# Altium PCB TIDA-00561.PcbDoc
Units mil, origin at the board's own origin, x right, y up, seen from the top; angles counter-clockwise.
Board outline 1527.56 x 1133.86 mil, 2 copper layers (Top Layer, Bottom Layer), stack 62 mil thick; 40 components, 27 nets, 121 pads, 25 vias.
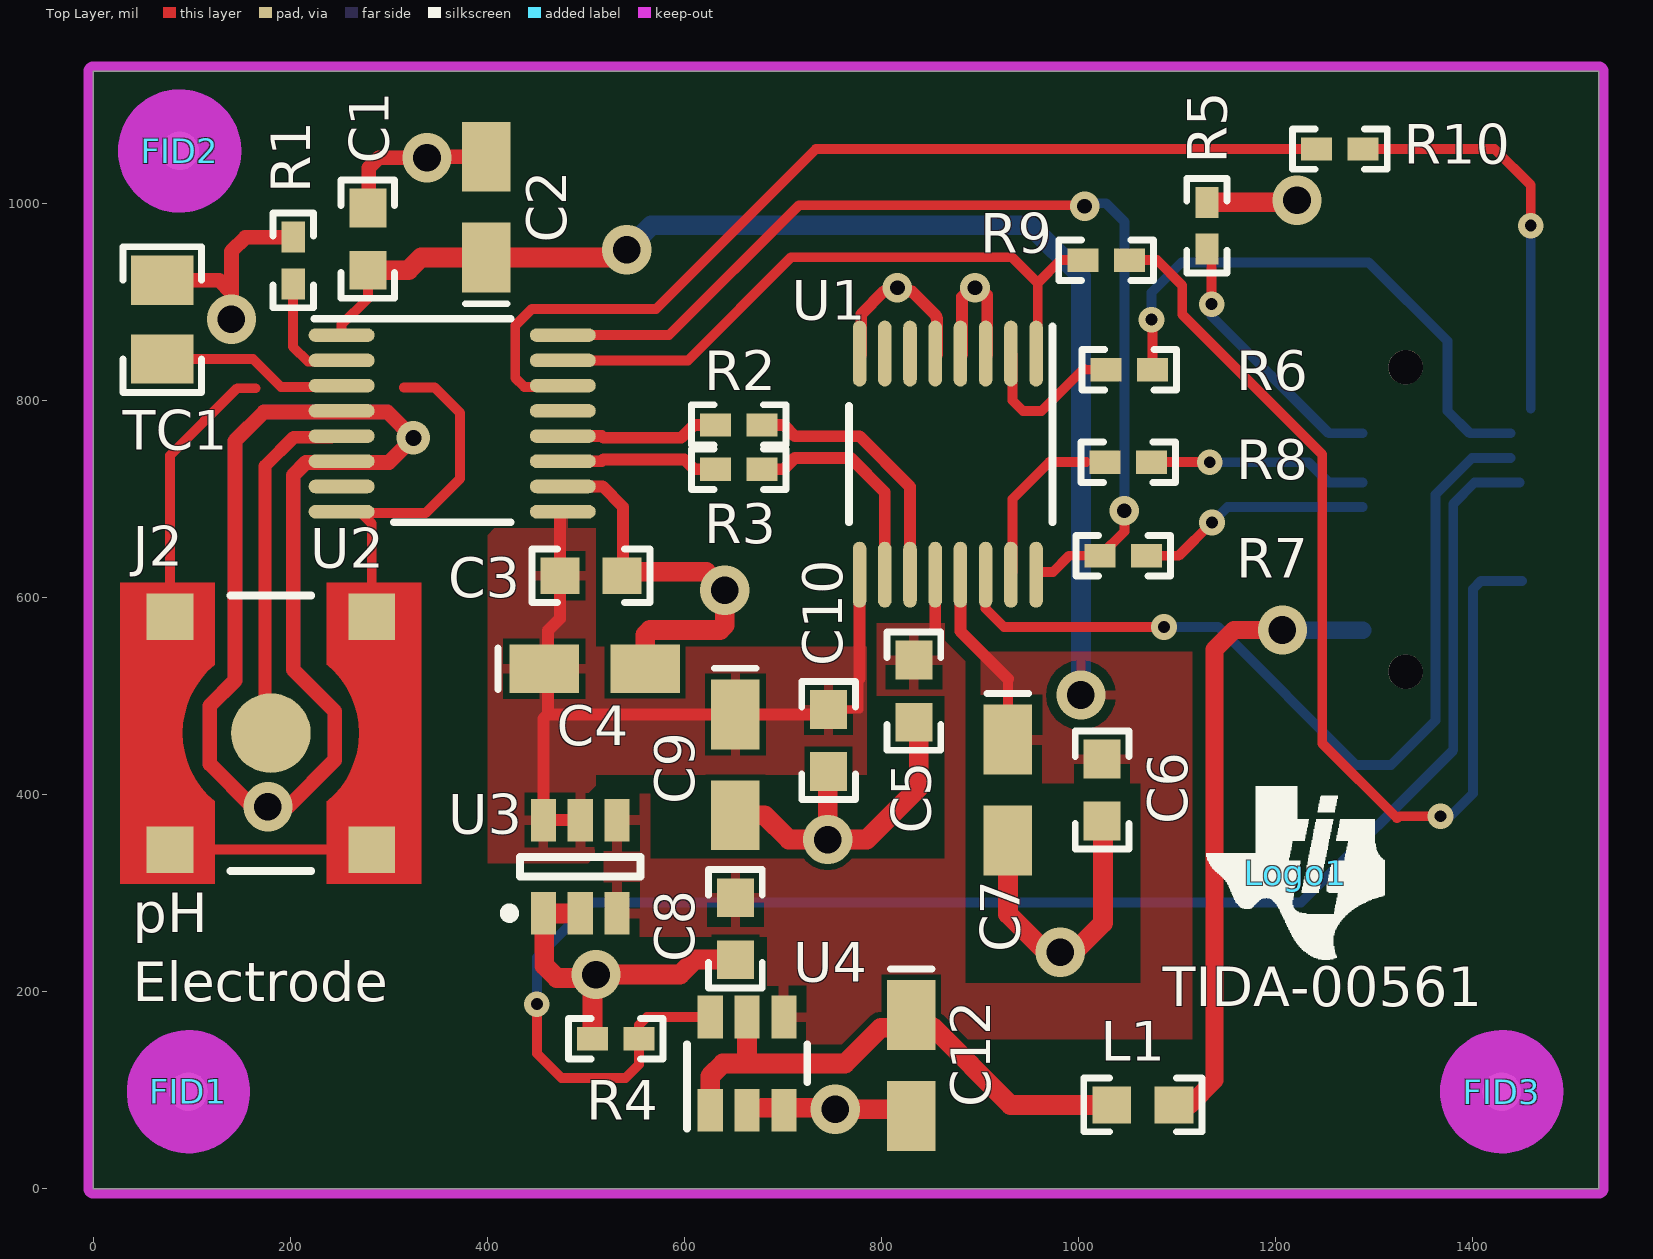
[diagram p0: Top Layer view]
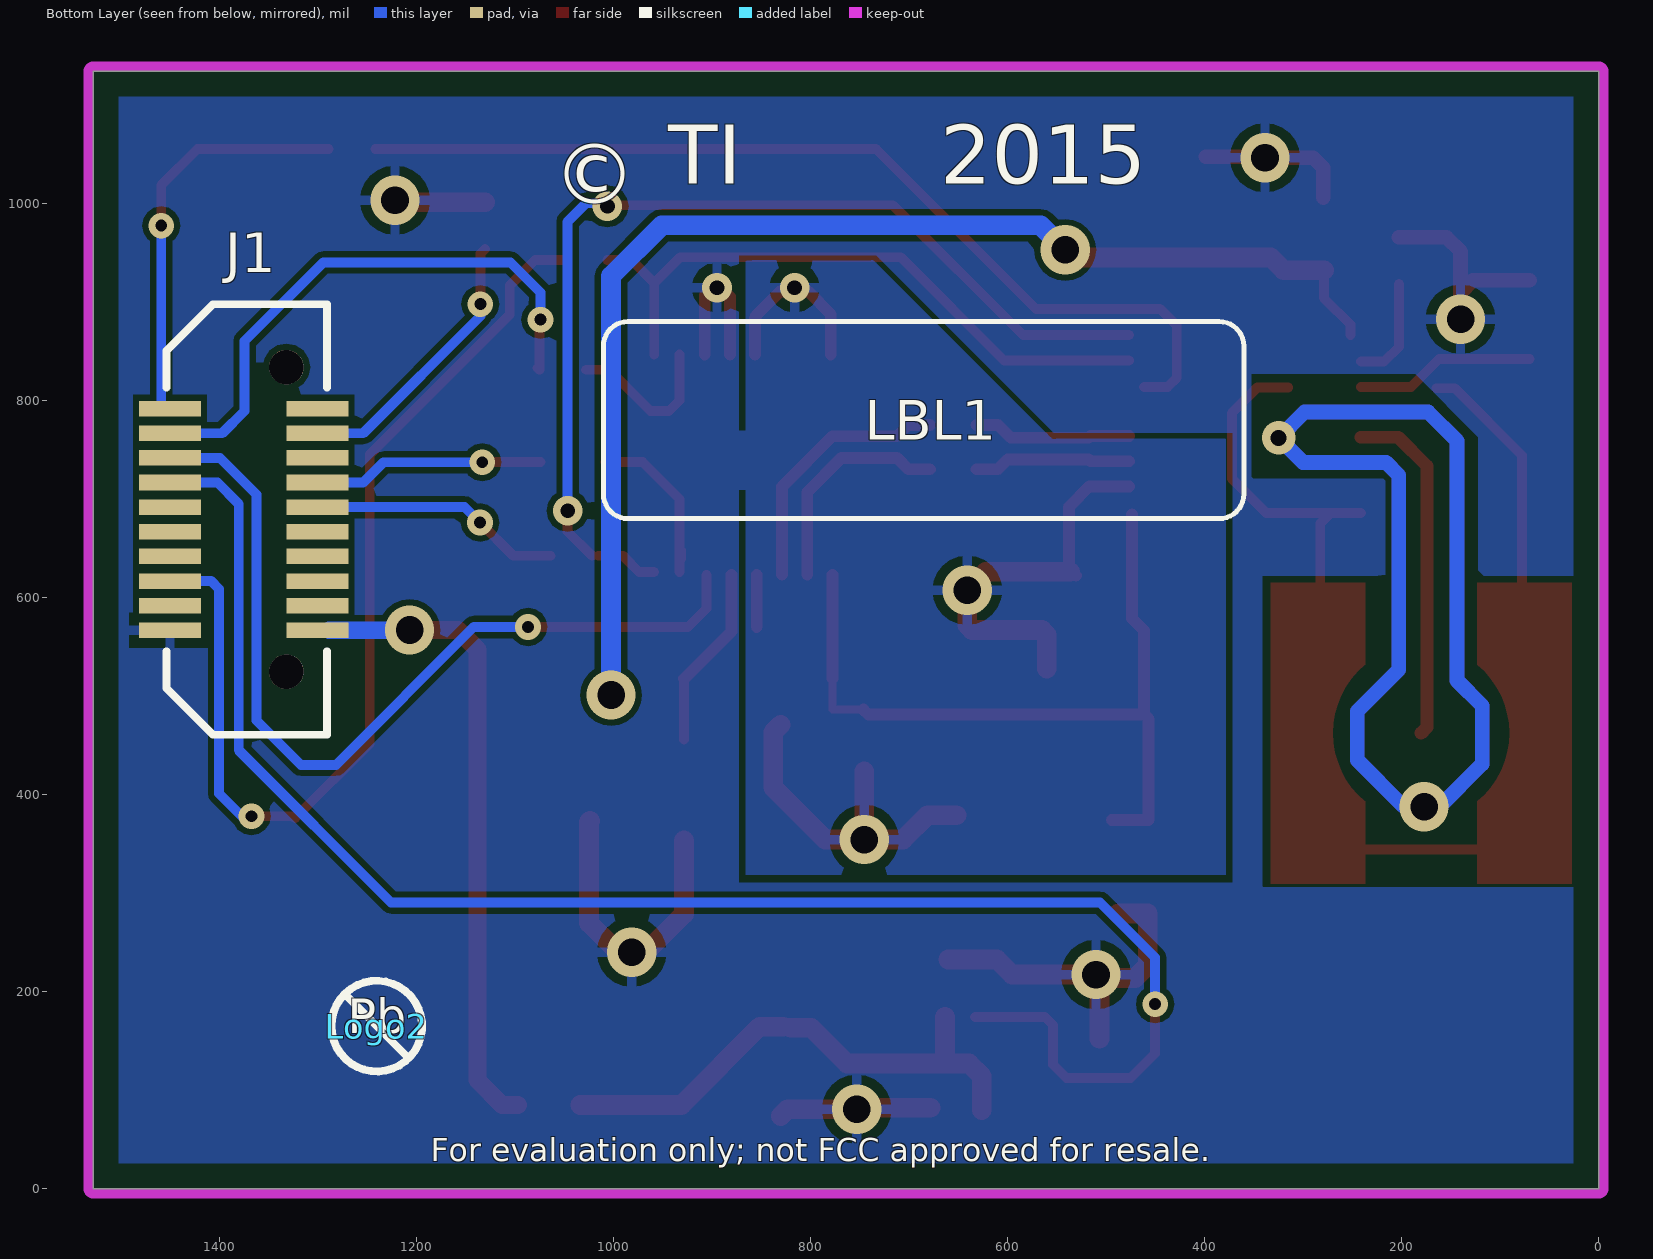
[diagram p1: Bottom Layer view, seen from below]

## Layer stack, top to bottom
Top Solder: solder mask 0.4, Solder Resist, Dk 3.5
Top Layer: signal copper 1.4
Dielectric1: core 59.2, FR-4, Dk 4.8
Bottom Layer: signal copper 1.4
Bottom Solder: solder mask 0.4, Solder Resist, Dk 3.5

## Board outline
0,0 1527.56,0 1527.56,1133.86 0,1133.86

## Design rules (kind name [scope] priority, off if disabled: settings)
AcuteAngle [All] p1: minimum=4.50000000000000E+0001 checktracksonly=FALSE
AssemblyTestPointUsage [All] p1: valid=2
Clearance Clearance_Keepouts [((IsTrack Or IsArc) And Not InPoly) And IsFree and IsKeepOut vs ((IsTrack Or IsArc) And Not InPoly) And IsFree and IsKeepOut] p1: gap=0
Clearance Clearance_BoardEdge_MountingHoles [OnCopper and InComponentClass('Mounting Holes') vs IsKeepOut] p2: gap=40
Clearance Clearance_BoardEdge_Poly [OnCopper and InPoly vs IsKeepOut] p3: gap=25
Clearance Clearance_BoardEdge [OnCopper and Not InComponentClass('Logo') and not InComponentClass('FiducialMark') and not InRegion(1000,500,4000,800) and Not IsKeepout vs IsKeepOut] p4: gap=25
Clearance Clearance_Poly [InPolygon] p5: gap=6
Clearance [All] p6: gap=7.87
ComponentClearance ComponentClearance_MountingHoles_FiducialMarks [InComponentClass('Mounting Holes') vs InComponentClass('FiducialMark')] p1: gap=50 collisioncheckmode=3 verticalgap=10 showdistances=FALSE
ComponentClearance ComponentClearance_Shunt [InComponentClass('Header') vs InComponentClass('Shunt')] p2: gap=0 collisioncheckmode=3 verticalgap=0 showdistances=FALSE
ComponentClearance ComponentClearance_Logo [InComponentClass('Logo')] p3: gap=50 collisioncheckmode=3 verticalgap=10 showdistances=FALSE
ComponentClearance ComponentClearance_ScrewToNut [(HasFootprint('NY PMS 440 0025 PH')) vs (HasFootprint('Keystone_1902C'))] p4: gap=5 collisioncheckmode=3 verticalgap=10 showdistances=FALSE
ComponentClearance ComponentClearance_MountingHoles [InComponentClass('Mounting Holes')] p5: gap=250 collisioncheckmode=3 verticalgap=100000 showdistances=FALSE
ComponentClearance ComponentClearance_SmallPassives [HasFootprint('0201*') or HasFootprint('0402*') or HasFootprint('0508') or HasFootprint('0603*') or HasFootprint('0612') or HasFootprint('0805*') or HasFootprint('0815*') or HasFootprint('0830*') or HasFootprint('1206*') or HasFootprint('1210*') or HasFootprint('1808*') or HasFootprint('1812*') or HasFootprint('1825*') or HasFootprint('2010*') or HasFootprint('2220*') or HasFootprint('2225*') or HasFootprint('2512*') or HasFootprint('2728*') or HasFootprint('3518*') vs HasFootprint('0201*') or HasFootprint('0402*') or HasFootprint('0508') or HasFootprint('0603*') or HasFootprint('0612') or HasFootprint('0805*') or HasFootprint('0815*') or HasFootprint('0830*') or HasFootprint('1206*') or HasFootprint('1210*') or HasFootprint('1808*') or HasFootprint('1812*') or HasFootprint('1825*') or HasFootprint('2010*') or HasFootprint('2220*') or HasFootprint('2225*') or HasFootprint('2512*') or HasFootprint('2728*') or HasFootprint('3518*')] p6: gap=20 collisioncheckmode=3 verticalgap=10 showdistances=FALSE
ComponentClearance ComponentClearance_THtoSMT [IsThruComponent vs IsSMTComponent] p7: gap=100 collisioncheckmode=3 verticalgap=30 showdistances=FALSE
ComponentClearance ComponentClearance_THtoTH [IsThruComponent vs IsThruComponent] p8: gap=118.11 collisioncheckmode=3 verticalgap=30 showdistances=FALSE
ComponentClearance [All] p9: gap=40 collisioncheckmode=3 verticalgap=10 showdistances=FALSE
DiffPairsRouting [All] p1: maxlimit=100 minlimit=10 mostfreqgap=10 toplayer_minwidth=12 toplayer_maxwidth=15 toplayer_prefwidth=15 bottomlayer_minwidth=12 bottomlayer_maxwidth=15 bottomlayer_prefwidth=15 maxuncoupledlength=1000
FabricationTestPointUsage TestPointUsage [All] p1: valid=2 allowmultiple=FALSE
FabricationTestpoint Testpoint [All] p1: side=3 testpointundercomponent=TRUE minsize=40 maxsize=100 preferedsize=60 minholesize=0 maxholesize=40 preferedholesize=32 testpointgrid=1 allowsidetop=TRUE allowsidebottom=TRUE usegrid=TRUE gridtolerance=0.01
FanoutControl Fanout_LCC [IsLCC] p1: bgadir=Out bgaviamode=Centered fanoutstyle=Auto fanoutdirection=Alternating viagrid=1 // Fanout_LCC (Default Rule)
FanoutControl Fanout_BGA [IsBGA] p2: bgadir=Out bgaviamode=Centered fanoutstyle=Auto fanoutdirection=Alternating viagrid=1 // Fanout_BGA (Default Rule)
FanoutControl Fanout_Default [All] p4: bgadir=Out bgaviamode=Centered fanoutstyle=Auto fanoutdirection=Alternating viagrid=1 // Fanout_Default (Default Rule)
FanoutControl Fanout_Small [(CompPinCount < 5)] p5: bgadir=Out bgaviamode=Centered fanoutstyle=Auto fanoutdirection=OutThenIn viagrid=1 // Fanout_Small (Default Rule)
HoleSize [All] p1: absolutevalues=TRUE maxlimit=251 minlimit=8 maxpercent=80.000 minpercent=20.000
MinimumAnnularRing MinimumAnnularRing_ThermalPadVias [IsVia and InAnyComponent] p1: minimumring=5.91
MinimumAnnularRing [All] p2: minimumring=7
MinimumSolderMaskSliver MinimumSolderMaskSliver_Logo [InComponentClass('Logo') vs InComponentClass('Logo')] p1: minsoldermaskwidth=0.7
MinimumSolderMaskSliver [All] p2: minsoldermaskwidth=3.94
NetAntennae [All] p1 off: netantennaetolerance=0
PlaneConnect [All] p1: planeconnectstyle=Relief reliefexpansion=10 reliefentries=4 reliefconductorwidth=10 reliefairgap=10
PolygonConnect [All] p1: connectstyle=Relief reliefconductorwidth=10 reliefentries=4 polygonreliefangle="90 Angle" airgapwidth=10
RoutingVias ThermalPadVias [IsVia and InAnyComponent] p1: holewidth=7.87 width=19.68 viastyle="Through Hole" minholewidth=7.87 minwidth=19.68 maxholewidth=12.99 maxwidth=23.62
RoutingVias [All] p2: holewidth=16 width=34 viastyle="Through Hole" minholewidth=7.87 minwidth=26 maxholewidth=40 maxwidth=65
SilkToBoardRegionClearance [Not ((IsComment or IsDesignator) And (Hide <> 'False')) and not InRegion(1000,500,4000,800)] p1:
SilkToSilkClearance SilkToSilkClearance_Pb-FreeLogo [(HasFootprint('Pb-Free_Overlay_Medium') OR HasFootprint('Pb-Free_Overlay_Small')) vs (HasFootprint('Pb-Free_Overlay_Medium') OR HasFootprint('Pb-Free_Overlay_Small'))] p1: silktosilkclearance=0
SilkToSilkClearance [All] p2: silktosilkclearance=5
SilkToSolderMaskClearance "Silk to Solder Mask Opening" [All] p1: minsilkscreentomaskgap=1 clearancetoexposedcopper=FALSE
SolderMaskExpansion [All] p1: expansion=1.97
UnpouredPolygon [All] p1: allowunpoured=FALSE
Width [All] p1: maxlimit=100 minlimit=6 preferedwidth=10 checkconnectedcopper=TRUE
13 further rules are at their usual default settings.

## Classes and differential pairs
component class Label: LBL1
component class AssemblyNote: ZZ1 ZZ2 ZZ3 ZZ4
component class Logo: Logo1
component class TIDA-00561_Hardware: FID1 FID2 FID3 LBL1 Logo1 Logo2 Logo3 ZZ1 ZZ2 ZZ3 ZZ4
component class FiducialMark: FID1 FID2 FID3
component class TIDA-00561_Wireless_pH: C1 C2 C3 C4 C5 C6 C7 C8 C9 C10 C12 J1 J2 L1 R1 R2 R3 R4 R5 R6 R7 R8 R9 R10 TC1 U1 U2 U3 U4
differential pair AIN: +AIN_P -AIN_N
differential pair VOUT: +VOUT_P -VOUT_N

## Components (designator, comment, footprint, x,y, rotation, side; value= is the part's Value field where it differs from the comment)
C1 "06035C104KAT2A" 0603 278.54,963.58 r90 top
C2 "293D106X0010A2TE3" 3216-18 398.62,996.06 r90 top
C3 "06035C104KAT2A" 0603 504.92,622.05 r0 top
C4 "293D106X0010A2TE3" 3216-18 508.8,527.56 r0 top
C5 "06035C104KAT2A" 0603 832.68,504.92 r270 top
C6 "06035C104KAT2A" 0603 1023.62,404.53 r270 top
C7 "293D106X0010A2TE3" 3216-18 928.15,404.53 r270 top
C8 "GRM188R71C474KA88D" 0603 651.57,263.78 r270 top
C9 "293D106X0010A2TE3" 3216-18 651.57,430.12 r270 top
C10 "06035C104KAT2A" 0603 746.06,454.72 r270 top
C12 "293D106X0010A2TE3" 3216-18 830,125 r270 top
FID1 "Fiducial" Fiducial10-30 96.46,98.43 r0 top
FID2 "Fiducial" Fiducial10-30 87.6,1053.15 r0 top
FID3 "Fiducial" Fiducial10-30 1429.13,98.43 r0 top
J1 "LSS-110-01-F-DV-A" Samtec_LSS-110-01-F-DV-A 1375,679.13 r90 bottom
J2 "CONSMA001-SMD-G" Linx_CONSMA001-SMD-G 180.11,462.27 r0 top
L1 "BLM18BB050SN1D" 0603 1065,85 r180 top
LBL1 "Size: 0.65\" x 0.20 \"" Label_650x200 685,780 r180 bottom
Logo1 "Texas Instruments" TI_Symbol_Overlay_Small 1220,320 r0 top
Logo2 "Pb-Free Symbol" Pb-Free_Overlay_Small 1240,165 r180 bottom
Logo3 "FCC disclaimer" FCC_disclaimer -4931.16,520 r180 bottom
R1 "RG1005P-101-B-T5" 0402 202.76,941.93 r270 top
R2 "CRCW04021K00JNED" 0402 655,775 r0 top
R3 "CRCW04021K00JNED" 0402 655,730 r0 top
R4 "CRCW04022M20JNED" 0402 530.23,152.27 r0 top
R5 "CRCW0402270KJNED" 0402 1130.11,977.27 r270 top
R6 "CRCW040247R0JNED" 0402 1051.32,830.99 r0 top
R7 "CRCW040247R0JNED" 0402 1045.11,642.27 r180 top
R8 "CRCW040247R0JNED" 0402 1050.11,737.27 r180 top
R9 "CRCW040247R0JNED" 0402 1027.7,942.27 r0 top
R10 "CRCW040247R0JNED" 0402 1265,1055 r0 top
TC1 "PTS080501B100RP100" 0805_HV 69.88,881.89 r90 top
U1 "ADS1120IPWR" PW0016A_N 867.11,735.27 r270 top
U2 "LMP91200MTX/NOPB" PW0016A_N 364.17,776.57 r0 top
U3 "REF3220AIDBVR" DBV0006A_N 494.09,326.77 r90 top
U4 "TS5A3159DBVR" DBV0006A_N 663.39,126.97 r90 top
ZZ1 "This Assembly Note is for PCB labels only" AssemblyNoteLabel 160,1565 r90 top
ZZ2 "These assemblies are ESD sensitive, ESD precautions shall be observed." AssemblyNote 165,1455 r90 top
ZZ3 "These assemblies must be clean and free from flux and all contaminants. Use of no clean flux is not acceptable." AssemblyNote 165,1355 r90 top
ZZ4 "These assemblies must comply with workmanship standards IPC-A-610 Class 2, unless otherwise specified." AssemblyNote 165,1260 r90 top

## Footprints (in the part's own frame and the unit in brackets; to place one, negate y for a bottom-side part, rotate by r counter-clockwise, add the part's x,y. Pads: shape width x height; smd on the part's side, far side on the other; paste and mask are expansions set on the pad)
0402 [mm] "0402 from SM-752 data"
  rect 0.8x0.6 smd: 1(-0.6,0) 2(0.6,0)
  silkscreen extent -1.22,-0.52 1.22,0.52, body extent -0.55,-0.3 0.55,0.3, height 0.6
0603 [mm] "0603 from SM-752 data"
  rect 1x0.95 smd: 1(-0.8,0) 2(0.8,0)
  silkscreen extent -1.52,-0.69 1.52,0.69, body extent -0.87,-0.47 0.87,0.47, height 0.85
0805_HV [mil] "0805 with 30mil clearance between pads"
  rect 50x63 smd: 1(-40,0) 2(40,0)
  silkscreen extent -74,-40 74,40, body extent -43,-29 43,29, height 43
3216-18 [mm] "Medium density IPC, based on Kemet T495 dimensions"
  rect 1.8x1.25 smd: 1(-1.3,0) 2(1.3,0)
  silkscreen extent -2.49,-0.54 -2.49,0.54, body extent -1.7,-0.9 1.7,0.9, height 1.8
AssemblyNote [mil] "Assembly Note"
AssemblyNoteLabel [mil] "Assembly Note for PCB Labels"
DBV0006A_N [mm] "SOT23, 6-Leads, Body 2.9x1.6mm, Pitch 0.95mm, Lead Span 2.8mm, IPC Medium Density"
  rect 1.1x0.65 smd: 1(-1.2,0.95) 2(-1.2,0) 3(-1.2,-0.95) 4(1.2,-0.95) 5(1.2,0) 6(1.2,0.95)
  silkscreen extent -1.32,-1.55 0.25,1.95, body extent -1.42,-1.46 1.42,1.46, height 1.11
FCC_disclaimer [mil]
Fiducial10-30 [mm]
  round 1 smd mask+1: 1(0,0)
  Top Layer keep-out circle w1.678: c0,0 r0.75
Label_650x200 [mil] "Thermal Transfer Label"
  round 1 on Mech14: 0(0,0)
  silkscreen extent -325,-100 325,100, body extent -326,-101 326,101, height 1
Linx_CONSMA001-SMD-G [mm] "SMD, 5-Leads, Body 7x7mm, Height 10.5mm"
  round 2.05 smd: 1(0,0)
  rect 1.2x1.2 smd: 2(-2.6,-3) 3(2.6,-3) 4(2.6,3) 5(-2.6,3)
  Top Layer region: -3.88,-3.88 -1.44,-3.88 -1.44,-1.761 -1.448,-1.761 -2.062,-0.974 -2.28,0 -2.062,0.974 -1.448,1.761 -1.448,1.761 -1.44,1.761 -1.44,3.88 -3.88,3.88
  Top Layer region: 3.88,-3.88 1.44,-3.88 1.44,-1.761 1.448,-1.761 2.062,-0.974 2.28,0 2.062,0.974 1.448,1.761 1.448,1.761 1.44,1.761 1.44,3.88 3.88,3.88
  silkscreen extent -1.04,-3.55 1.04,3.55, body extent -3.55,-3.55 3.55,3.55, height 10.5
Pb-Free_Overlay_Small [mil]
  silkscreen extent -46,-46 46,46
PW0016A_N [mm] "TSOP, 16-Leads, Body 5x4.4mm, Pitch 0.65mm, IPC Medium Density"
  oval 1.7x0.35 smd: 1(-2.85,2.275) 2(-2.85,1.625) 3(-2.85,0.975) 4(-2.85,0.325) 5(-2.85,-0.325) 6(-2.85,-0.975) 7(-2.85,-1.625) 8(-2.85,-2.275) 9(2.85,-2.275) 10(2.85,-1.625) 11(2.85,-0.975) 12(2.85,-0.325) 13(2.85,0.325) 14(2.85,0.975) 15(2.85,1.625) 16(2.85,2.275)
  silkscreen extent -3.55,-2.55 1.5,2.7, body extent -3.21,-2.5 3.21,2.5, height 0.98
Samtec_LSS-110-01-F-DV-A [mm] "Samtec"
  rect 0.4x1.6 smd: 1(-2.857,1.9) 2(-2.857,-1.9) 3(-2.222,1.9) 4(-2.222,-1.9) 5(-1.587,1.9) 6(-1.588,-1.9) 7(-0.952,1.9) 8(-0.953,-1.9) 9(-0.317,1.9) 10(-0.318,-1.9) 11(0.318,1.9) 12(0.317,-1.9) 13(0.953,1.9) 14(0.952,-1.9) 15(1.588,1.9) 16(1.587,-1.9) 17(2.222,1.9) 18(2.222,-1.9) 19(2.857,1.9) 20(2.857,-1.9)
  round 0.89 hole 0.89 unplated: MH-1(3.925,-1.1) MH-2(-3.925,-1.1)
  silkscreen extent -5.55,-2.15 5.55,1.99, body extent -5.55,-2.3 5.55,2.3, height 4.46
TI_Symbol_Overlay_Small [mil]
  silkscreen extent -90,-88 91,88

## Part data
C1 C3 C5 C6 C10: "CAP, CERM, 0.1 µF, 50 V, +/- 10%, X7R, 0603"
C2 C4 C7 C9 C12: "CAP, TA, 10uF, 10V, +/-20%, 3.4 ohm, SMD"
C8: "CAP, CERM, 0.47 µF, 16 V, +/- 10%, X7R, 0603"
FID1 FID2 FID3: "Fiducial mark.  There is nothing to buy or mount."
J1: "Terminal/Socket Combo, 25mil, 10x2, Gold, SMT"
J2: "Jack, SMA, PCB, Gold, SMT"
L1: "Ferrite Bead, 5 ohm @ 100 MHz, 0.7 A, 0603"
LBL1: library part THT-14-423-10, "Thermal Transfer Printable Labels, 0.650\" W x 0.200\" H - 10,000 per roll"
Logo1: library part TI_Logo, "Texas Instrument Corporate Signature"
Logo2: library part Pb-Free
Logo3: library part FCC_disclaimer, "FCC_disclaimer"
R1: "RES, 100, 0.1%, 0.063 W, 0402"
R2 R3: "RES, 1.0 k, 5%, 0.063 W, 0402"
R4: "RES, 2.2 M, 5%, 0.063 W, 0402"
R5: "RES, 270 k, 5%, 0.063 W, 0402"
R6 R7 R8 R9 R10: "RES, 47, 5%, 0.063 W, 0402"
TC1: "Temperature Sensor, 100ohm, 1%, TC=+3850ppm, 0805, SMT"
U1: "Low-Power, Low-Noise, 16-Bit ADC for Small-Signal Sensors, PW0016A"
U2: "Configurable AFE for Low-Power Chemical Sensing Applications, PW0016A"
U3: "2.048 V, 4 ppm / degC, 100 uA Series (Bandgap) Voltage Reference, -40 to 125 degC, 6-pin SOT-23 (DBV), Green (RoHS & no Sb/Br)"
U4: "1-? SPDT Analog Switch, DBV0006A"
ZZ1: library part AssemblyNoteLabel
ZZ2 ZZ3 ZZ4: library part AssemblyNote

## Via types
v1: diameter 50, hole 28, Top Layer to Bottom Layer, 12 vias
v2: diameter 26, hole 12, Top Layer to Bottom Layer, 8 vias
v3: diameter 30, hole 15, Top Layer to Bottom Layer, 4 vias
v4: diameter 34, hole 16, Top Layer to Bottom Layer, 1 vias

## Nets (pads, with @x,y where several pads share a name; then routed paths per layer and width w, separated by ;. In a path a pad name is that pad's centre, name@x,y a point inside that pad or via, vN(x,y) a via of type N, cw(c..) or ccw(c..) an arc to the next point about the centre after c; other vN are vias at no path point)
3V_PWR: C1.1 C2.1 C5.1 C6.1 C7.1 C8.1 U1.12 U1.13 U2.1 U3.3 U3.4 U4.4 | length 1517
  Top Layer w10: U2.1 251.97,876.97 278.54,903.54 C1.1 ; C7.1 928.15,517.44
  Top Layer w12: 854.31,570 U1.12 ; U1.13 879.9,565.69 928.15,517.44
  Top Layer w20: C1.1 319.88,932.09 332.68,944.88 C2.1 533.46,944.88 v1(541.34,952.76)
  Bottom Layer w20: v1(541.34,952.76) 566.18,977.6 950.79,977.6 1002.2,926.19 v1(1002.2,500.98) v1@1012.8,500.98
AIN_N: R3.2 U1.10 | length 227.4
  Top Layer w12: R3.2 700.37,730 711.87,741.5 768.5,741.5 803.13,706.87 U1.10
AIN_P: R2.2 U1.11 | length 265.4
  Top Layer w12: R2.2 700.37,775 711.87,763.5 777.61,763.5 828.72,712.39 U1.11
CS_1: R6.1 U1.2 | length 164.2
  Top Layer w10: U1.2@932.74,846.38 932.74,799.9 943.35,789.29 962.13,789.29 1005.11,832.27 1006.39,830.99 R6.1
CS_2: R10.1 U2.14 | length 977.8
  Top Layer w10: U2.14@461.48,813.66 437.32,813.66 428.15,822.83 428.15,875.98 444.88,892.72 570.87,892.72 733.15,1055 R10.1@1241.49,1055
DATA_READY: J1.15 U1.14 | length 896.2
  Top Layer w10: U1.14 905.5,588.6 924.09,570 v2(1086.43,570)
  Bottom Layer w10: v2(1086.43,570) 1141.61,570 1281.5,430.12 1316.93,430.12 1362.09,475.28 1362.09,704.61 1399.11,741.63 J1.15@1438.19,741.63
GND: C1.2 C2.2 C3.2 C4.2 C5.2 C6.2 C7.2 C8.2 C9.2 C10.2 C12.2 J1.1 R1.1 R4.1 R5.1 TC1.2 U1.3 U1.4 U1.5 U1.8 U2.10 U3.1 U3.2 U4.2 U4.3 | length 2368.5
  Top Layer w12: U2.10 516.73,712.6 537.4,691.93 537.4,628.94 C3.2@530.51,622.05 ; U1.8@779.2,846.38 779.2,887.46 802.23,910.49 830.65,910.49 855.32,885.83 855.32,883.86 855.97,883.21 U1.5@855.97,846.38 ; U1.4@881.56,846.38 881.56,905.18 895.18,918.8 907.15,906.83 U1.3@907.15,846.38
  Top Layer w15: TC1.2 127.69,921.89 140.11,909.47 ; v1(140.11,882.27) 140.11,909.47 ; R1.1 154.53,965.55 140.11,951.13 140.11,909.47 ; C1.2@279.53,1005.91 279.53,1035.99 289.8,1046.26 v1(338.58,1046.26) 339.57,1047.24 C2.2
  Top Layer w20: U3.2@487.29,279.3 457.68,279.3 457.68,226.42 470.33,213.77 v1@506.61,213.77 ; R4.1 v1@506.61,213.77 ; C3.2@536.42,625.98 621.9,625.98 v1(640.61,607.27) 640.61,571.72 635.83,566.93 564.96,566.93 559.98,561.94 C4.2 ; C9.2 681.1,378.94 705.79,354.25 v1(745.16,354.25) ; C8.2@660.11,232.59 610.54,232.59 595.23,217.27 v1(510.11,217.27) v1@506.61,213.77 ; 678.09,82.16 v1@752.87,82.16 ; C10.2@745.16,423.5 v1(745.16,354.25) 784.83,354.33 837.6,407.1 837.6,463.29 C5.2@830.11,470.78 ; v1(752.87,80.6) 823.22,80.6 C12.2 ; C7.2 928.15,278.54 966.63,240.06 v1(981.2,240.06) 994.98,240.06 1024.61,269.68 1024.61,372.05 C6.2 ; R5.1 v1@1219.4,1000.9
  other v1: 1221.46,1002.95
  other v3: 815.94,914.37 894.68,914.37
GUARD: U2.4 U2.6 | length 2309.6
  Top Layer w15: v1@183.1,387.68 v1(177.17,387.68) ; v1(177.17,387.68) 161.53,387.68 118.11,431.1 118.11,490.16 143.7,515.75 143.7,758.86 172.91,788.07 298.55,788.07 v4(324.8,761.81) 299.88,736.89 215.68,736.89 202.76,723.96 202.76,526.57 245,484.33 245,435 197.68,387.68 v1(177.17,387.68)
  Bottom Layer w15: v1@175.2,388.78 198.78,388.78 245,435 245,484.33 202.76,526.57 202.76,723.96 215.68,736.89 299.88,736.89 v4(324.8,761.81) 298.55,788.07 172.91,788.07 143.7,758.86 143.7,515.75 118.11,490.16 118.11,431.1 161.53,387.68 v1(177.17,387.68)
MISO: R8.2 U1.15 | length 173
  Top Layer w10: U1.15@931.11,638.94 U1.15@931.11,647.48 ; U1.15@932.74,625.9 932.74,699.9 970.11,737.27 1007.74,737.27
MOSI: R7.2 U1.16 U2.16 | length 1046.3
  Top Layer w10: U2.16 584.1,866.14 715.99,998.03 v3@1005.91,998.03 ; U1.16@958.33,625.9 973.74,625.9 990.11,642.27 R7.2@1015.11,642.27 ; R7.2 1046.26,667.05 v3(1046.26,687.99)
  Bottom Layer w10: v3(1005.91,997.05) 1008.86,1000 1027.56,1000 1046.26,981.3 v3(1046.26,687.99)
NetJ1_2: J1.2 L1.1 | length 647.6
  Top Layer w18: L1.1 1112.8,85 1137.8,110 1137.8,547.24 1157.48,566.93 v1(1206.69,566.93)
  Bottom Layer w18: v1(1206.69,566.93) 1206.99,566.63 J1.2@1288.19,566.63
NetJ1_5: J1.5 R9.2 | length 1055.1
  Top Layer w10: R9.2 1079.38,942.27 1105,916.65 1105,887.13 1247.05,745.08 1247.05,451.77 1322.83,375.98 1324.8,377.95 v2(1367.13,377.95)
  Bottom Layer w10: v2(1367.13,377.95) 1365.16,377.95 1364.17,376.97 1370.08,371.06 1400,400.98 1400,608.66 1407.97,616.63 J1.5
NetJ1_12: J1.12 R7.1 | length 244.9
  Top Layer w10: R7.1@1063.73,642.27 1101.42,642.27 v2(1135.18,676.03)
  Bottom Layer w10: v2(1135.18,676.03) 1150.78,691.63 J1.12@1288.19,691.63
NetJ1_14: J1.14 R8.1 | length 223
  Top Layer w10: R8.1 1132.81,737.27 v2(1132.87,737.2)
  Bottom Layer w10: v2(1132.87,737.2) 1233.12,737.2 1253.69,716.63 J1.14@1288.19,716.63
NetJ1_17: J1.17 R6.2 | length 571.7
  Top Layer w10: v2(1073.82,881.89) 1074.95,880.76 R6.2 R6.2@1076.73,832.77
  Bottom Layer w10: v2(1073.82,881.89) 1073.82,909.36 1104.42,939.96 1294.29,939.96 1374.02,860.24 1374.02,789.37 1396.75,766.63 J1.17@1438.19,766.63
NetJ1_19: J1.19 R10.2 | length 411.8
  Top Layer w10: R10.2@1288.73,1055 1422.04,1055 1458.66,1018.38 v2(1458.66,977.36)
  Bottom Layer w10: J1.19@1458.66,791.63 v2(1458.66,977.36)
NetJ2_1: J2.1 U2.5 | length 352.3
  Top Layer w13: J2.1 174.21,468.17 174.21,733.27 203.42,762.48 U2.5@241.01,762.48
NetJ2_2: J2.2 J2.3 J2.4 J2.5 U2.8 | length 873.1
  Top Layer w10: J2.2 J2.3 ; J2.5 77.75,744.09 145.95,812.29 164.37,812.29 ; U2.8@241.01,685.71 U2.8@271.7,685.71 ; J2.4 282.47,674.94 U2.8@271.7,685.71 ; 314.96,812.99 346.46,812.99 372.05,787.4 372.05,720.47 337.28,685.71 U2.8@271.7,685.71
NetR1_2: R1.2 U2.2 | length 108.5
  Top Layer w10: R1.2 202.76,854.33 217.84,839.25 U2.2@241.01,839.25
NetTC1_1: TC1.1 U2.3 | length 182.8
  Top Layer w10: TC1.1 162.05,841.89 190.28,813.66 U2.3@241.01,813.66
PWR_UP_CHIP: J1.13 R4.2 U4.6 | length 1683.1
  Top Layer w10: v2(450.11,187.27) 450.11,137.27 475.11,112.27 540.11,112.27 553.85,126.01 R4.2 553.85,166.05 562.01,174.21 U4.6@632.87,174.21
  Bottom Layer w10: v2(450.11,187.27) 450.11,234.56 505.91,290.35 1225.35,290.35 1379.97,444.97 1379.97,694.97 1401.63,716.63 J1.13@1447.56,716.63
SCLK: R9.1 U1.1 U2.15 | length 664.4
  Top Layer w10: U2.15 603.39,840.55 708.11,945.27 932.11,945.27 958.33,919.05 981.55,942.27 R9.1@1006.07,942.27 ; U1.1@958.33,846.38 958.33,917.27
SKIN_ID: J1.18 R5.2 | length 272.7
  Top Layer w10: R5.2 1134.84,948.92 v2(1134.84,897.64)
  Bottom Layer w10: v2(1134.84,897.64) 1134.84,885.48 1253.69,766.63 J1.18@1288.19,766.63
VDD_SENSORTAG: C12.1 L1.2 U4.1 U4.5 | length 535.2
  Top Layer w20: U4.1 625.98,114.17 638.78,126.97 762.8,126.97 799.21,163.39 C12.1@819.88,163.39 ; 663.29,126.97 U4.5 ; C12.1@827.19,164.37 851.38,164.37 930.75,85 L1.2
VOUT_N: R3.1 U2.11 | length 159.9
  Top Layer w12: U2.11 515.84,738.19 517.64,739.98 599.65,739.98 609.63,730 R3.1
VOUT_P: R2.1 U2.12 | length 161.1
  Top Layer w12: U2.12 515.84,763.78 517.64,761.98 596.61,761.98 609.63,775 R2.1
VREF_2.048V: C3.1 C4.1 C9.1 C10.1 U1.9 U2.9 U3.5 U3.6 | length 809.5
  Top Layer w8: C10.1 777.54,486.22 777.54,517.7
  Top Layer w12: U2.9@473.43,684.06 C3.1 473.43,578.43 461.3,566.3 461.3,481.3 ; U3.5 U3.6 456.69,476.69 461.3,481.3 ; C10.1 741.14,481.3 C9.1 461.3,481.3 ; 777.54,517.7 U1.9
pads on no net: FID1.1 FID2.1 FID3.1 J1.3 J1.4 J1.6 J1.7 J1.8 J1.9 J1.10 J1.11 J1.16 J1.20 J1.MH-1 J1.MH-2 LBL1.0 U1.6 U1.7 U2.7 U2.13

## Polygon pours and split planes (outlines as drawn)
VREF_2.048V on Top Layer "VREF1" (solid, remove dead copper, pour order 8): 400,670 510,670 510,330 400,330
3V_PWR on Top Layer "Top Layer-No Net" (solid, pour order 11): 900.59,545 900.59,411.42 1062.99,411.42 1062.99,267.72 1062.99,208.66 884.84,208.66 884.84,151.57 1115,151.57 1115,545
3V_PWR on Top Layer "Top Layer-No Net 2" (solid, remove dead copper, pour order 10): 864.17,573.82 844.49,573.82 795,573.82 795,500 864.17,500 864.17,335 564.96,335 564.96,400.59 517.72,400.59 517.72,255.91 684.06,255.91 684.06,146.65 884.84,146.65 884.84,235.24 884.84,535.43 864.17,556.1
VREF_2.048V on Top Layer "VREF2" (solid, remove dead copper, pour order 9): 505,550 785,550 785,420 505,420
GND on Bottom Layer "Bottom Layer-No Net" (solid, remove dead copper, pour order 7): 0,0 1537.4,0 1537.4,1133.86 0,1133.86

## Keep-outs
Keep-Out Layer:
  lines w10: -5,0 ccw(c0,0) 0,-5 ; -5,0 ccw(c0,0) 0,-5 ; -5,0 -5,1133.86 ; -5,1133.86 cw(c0,1133.86) 0,1138.86 ; -5,1133.86 cw(c0,1133.86) 0,1138.86 ; 0,-5 1527.56,-5 ; 0,1138.86 1527.56,1138.86 ; 1527.56,-5 ccw(c1527.56,0) 1532.56,0 ; 1527.56,-5 ccw(c1527.56,0) 1532.56,0 ; 1527.56,1138.86 cw(c1527.56,1133.86) 1532.56,1133.86 ; 1527.56,1138.86 cw(c1527.56,1133.86) 1532.56,1133.86 ; 1532.56,0 1532.56,1133.86
  text ".Layer_Name" at 577,-858.49 h60

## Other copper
Top Layer:
  text ".Layer_Name" at 577,-858.49 h60
Bottom Layer:
  pour cut-out: 866.14,708.66 872.05,708.66 872.05,311.02 372.05,311.02 372.05,766.73 553.15,766.73 733.27,946.85 872.05,946.85 872.05,769.68 866.14,769.68 866.14,941.93 735.24,941.93 554.13,760.83 377.95,760.83 377.95,317.91 866.14,317.91
  pour cut-out: 352.36,826.77 186.02,826.77 122.05,762.8 122.05,622.05 22.64,622.05 21.65,623.03 21.65,306.1 340.55,306.1 341.54,307.09 341.54,622.05 215.55,622.05 216.54,623.03 216.54,720.47 350.39,720.47 352.36,722.44
  text ".Layer_Name" at 577,-858.49 h60

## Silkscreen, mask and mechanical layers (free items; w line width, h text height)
Top Overlay:
  text "pH" at 40,260 h40
  text "Electrode" at 40,190 h40
  text "TIDA-00561" at 1085,185 h40
  text ".Layer_Name" at 577,-858.49 h60
Bottom Overlay:
  text "©" at 1061.02,1080.71 h105 r180
  text "2015" at 668.31,1019.68 h60
  text "TI" at 944.31,1019.68 h60
  text ".Layer_Name" at 577,-858.49 h60
Top Paste:
  text ".Layer_Name" at 577,-858.49 h60
Bottom Paste:
  text ".Layer_Name" at 577,-858.49 h60
Top Solder:
  text ".Layer_Name" at 577,-858.49 h60
  text ".Layer_Name" at 577,-858.49 h60
Bottom Solder:
  text ".Layer_Name" at 577,-858.49 h60
Drill Guide:
  text ".Layer_Name" at 577,-858.49 h60
M1 Board Outline:
  the board outline again, w10
  text ".Layer_Name" at 577,-858.49 h60
M2 Board Dimensions:
  rectangle: -0.5,-285.5 124.5,-160.5
  rectangle: 124.5,-410.5 499.5,-285.5
  lines w7: -0.5,-285.5 999.5,-285.5 ; 124.5,-410.5 124.5,-160.5 ; 249.5,-410.5 249.5,-160.5 ; 499.5,-410.5 499.5,-160.5 ; 749.5,-410.5 749.5,-160.5 ; -0.5,-410.5 999.5,-410.5 999.5,-160.5 -0.5,-160.5 -0.5,-410.5
  lines w10: -0.5,-475.5 -0.5,-455.5 ; 59.5,-485.5 -0.5,-465.5 ; 59.5,-445.5 -0.5,-465.5 ; 223.58,-465.5 -0.5,-465.5 ; 775.42,-465.5 999.5,-465.5 ; 939.5,-485.5 999.5,-465.5 ; 939.5,-445.5 999.5,-465.5 ; 999.5,-475.5 999.5,-455.5 ; -5,0 ccw(c0,0) 0,-5 ; -5,0 ccw(c0,0) 0,-5 ; -5,0 -5,1133.86 ; -5,1133.86 cw(c0,1133.86) 0,1138.86 ; -5,1133.86 cw(c0,1133.86) 0,1138.86 ; 0,-5 1527.56,-5 ; 0,1138.86 1527.56,1138.86 ; 1527.56,-5 ccw(c1527.56,0) 1532.56,0 ; 1527.56,-5 ccw(c1527.56,0) 1532.56,0 ; 1527.56,1138.86 cw(c1527.56,1133.86) 1532.56,1133.86 ; 1527.56,1138.86 cw(c1527.56,1133.86) 1532.56,1133.86 ; 1532.56,0 1532.56,1133.86
  text "1000 (mil)" at 233.58,-501.49 h60
  text ".Layer_Name" at 577,-858.49 h60
M3 3D STEP Top:
  text ".Layer_Name" at 577,-858.49 h60
M4 3D STEP Bottom:
  text ".Layer_Name" at 577,-858.49 h60
M5 Assembly Top:
  lines w10: -292,-930.17 6308,-930.17 ; -292,-726.83 6310,-726.83 ; -292,-523.5 -292,-1133.5 3713,-1133.5 6310,-1133.5 6310,-523.5 -291.5,-523.5 -291.5,-1133.5 1284,-1133.5 ; 2173,-1133.5 2173,-523.5 ; 3440,-726.83 3440,-523.5 ; 4280,-726.83 4280,-523.5 ; 4902,-1140 4902,-937.17
  text "COMPONENTS MARKED 'DNP' SHOULD NOT BE POPULATED." at 1153.5,-318.5 h60
  text "ASSEMBLY VARIANT:" at 1153,-434 h60
  text ".VariantName" at 2189,-434 h60
  text "PCB VIEWED FROM TOP SIDE" at -228.5,-655.67 h60
  text "BOARD #:" at 2248,-655.67 h60
  text ".PRJ_Number" at 2793.5,-655.67 h60
  text "REV:" at 3638,-655.67 h60
  text ".PCB_Rev" at 3929.5,-655.67 h60
  text "SVN REV:" at 4476,-655.67 h60
  text ".VersionControl_RevNumber" at 4982,-655.67 h60
  text "IGNORE ->" at -228.5,-858.49 h60
  text "PLOT NAME =" at -228.5,-1064.34 h60
  text ".plot_File_Name" at 577,-1064.34 h60
  text "GENERATED    :" at 2250,-1064.34 h60
  text ".Print_Date" at 3119.5,-1064.34 h60
  text ".Print_Time" at 3848.5,-1064.34 h60
  text "TEXAS INSTRUMENTS" at 5113,-1064.34 h60
M6 Assembly Bottom:
  lines w10: -292.5,-727.33 6309.5,-727.33 ; -290.5,-930.67 6309.5,-930.67 ; 1115.5,-1140.5 1115.5,-937.67 ; 1737.5,-727.33 1737.5,-524 ; 2577.5,-727.33 2577.5,-524 ; 3844.5,-1134 3844.5,-524 ; 4733.5,-1134 6309,-1134 6309,-524 -292.5,-524 -292.5,-1134 2304.5,-1134 6309.5,-1134 6309.5,-524
  text "COMPONENTS MARKED 'DNP' SHOULD NOT BE POPULATED." at 6102,-318 h60
  text ".VariantName" at 5058,-434 h60
  text "ASSEMBLY VARIANT:" at 6097,-434 h60
  text ".VersionControl_RevNumber" at 1035.5,-656.17 h60
  text "SVN REV:" at 1541.5,-656.17 h60
  text ".PCB_Rev" at 2088,-656.17 h60
  text "REV:" at 2379.5,-656.17 h60
  text ".PRJ_Number" at 3224,-656.17 h60
  text "BOARD #:" at 3769.5,-656.17 h60
  text "PCB VIEWED FROM BOTTOM SIDE" at 6246,-656.17 h60
  text "IGNORE ->" at 2547.85,-858.49 h60
  text "TEXAS INSTRUMENTS" at 904.5,-1064.84 h60
  text ".Print_Time" at 2169,-1064.84 h60
  text ".Print_Date" at 2898,-1064.84 h60
  text "GENERATED    :" at 3767.5,-1064.84 h60
  text ".plot_File_Name" at 5440.5,-1064.84 h60
  text "PLOT NAME =" at 6246,-1064.84 h60
M9 Title Sheet:
  drawing of 57 lines, arcs and shapes, not listed
  text "1" at 739.84,8036.5 h70
  text "2" at 3235.5,8036.5 h70
  text "3" at 5724.84,8036.5 h70
  text "4" at 8231.51,8036.5 h70
  text "5" at 10730.5,8036.5 h70
  text "6" at 13235.5,8036.5 h70
  text "A" at -416.5,6893.5 h70
  text "A" at 14383.5,6893.5 h70
  text "B" at -416.5,4513.5 h70
  text "B" at 14383.5,4513.5 h70
  text "C" at -416.5,2138.5 h70
  text "C" at 14383.5,2138.5 h70
  text "PROJECT TITLE:" at 11343.5,277.5 h45
  text ".PRJ_Title" at 11393.5,144.17 h70
  text "DESIGNED FOR:" at 11343.5,-23.5 h45
  text ".PRJ_Customer" at 11393.5,-163.5 h70
  text "D" at -416.5,-231.5 h70
  text "D" at 14383.5,-231.5 h70
  text "FILE NAME:" at 11343.5,-323.5 h45
  text ".PCB_File_Name_No_Path" at 11393.5,-443.5 h70
  text "Texas Instruments (TI) and/or its licensors do not warrant the accuracy or completeness of this specification" at 6374,-605.34 h45
  text "ENGINEER:" at 11343.5,-613.5 h45
  text "LAYOUT BY:" at 12848.5,-613.5 h45
  text "or any information contained therein. TI and/or its licensors do not warrant that this design will meet" at 6329.01,-718 h45
  text ".PRJ_Engineer" at 11393.5,-768.49 h70
  text ".PCB_Layout" at 12899,-768.49 h70
  text "the specifications, will be suitable for your application or fit for any particular purpose, or will operate in" at 6329.01,-830.67 h45
  text ".Layer_Name" at 577,-858.49 h60
  text "ALTIUM DESIGNER VERSION:" at 12848.5,-923.5 h45
  text "an implementation. TI and/or its licensors do not warrant that the design is production worthy. You should" at 6329.01,-943.33 h45
  text "completely validate and test your design implementation to confirm the system functionality for your application." at 6374,-1056 h45
  text ".print_Scale" at 11393.5,-1056.83 h70
  text ".Application_BuildNumber" at 12899,-1056.83 h70
  text "1" at 739.84,-1263.5 h70
  text "2" at 3235.5,-1263.5 h70
  text "3" at 5724.84,-1263.5 h70
  text "4" at 8231.51,-1263.5 h70
  text "5" at 10730.5,-1263.5 h70
  text "6" at 13235.5,-1263.5 h70
M10 Fab Notes:
  drawing of 212 lines, arcs and shapes, not listed
  text "DESIGN INFORMATION" at 12381.02,6810 h60
  text "(REFER ALSO ARRAY/PANEL PROFILING INFORMATION)" at 12019.46,6648.29 h60
  text "BOARD SIZE" at 11333.46,6644 h60
  text "3450MIL" at 11795.78,6516.18 h60
  text "X" at 12301.46,6516.18 h60
  text "4950MIL" at 12532.78,6516.18 h60
  text "Number of Layers :" at 11736.46,6319 h60
  text "2" at 12831.27,6309 h60
  text "MIN. TRACK WIDTH:" at 11736.46,6180 h60
  text "8" at 12832.7,6180 h60
  text "MIL" at 12987.46,6180 h60
  text "MIN. CLEARANCE:" at 11736.46,6048 h60
  text "8" at 12832.7,6048 h60
  text "MIL" at 12987.46,6048 h60
  text "MIN. VIA PAD SIZE:" at 11736.46,5916 h60
  text "24" at 12802.71,5916 h60
  text "MIL" at 12987.46,5916 h60
  text "0.05mm (2MIL)" at 12431.46,5774.29 h60
  text "MINIMUM ANNULAR RING" at 11407.23,5770 h60
  text "EXTERNAL" at 13139.46,5770 h60
  text "PER" at 11607.23,5652 h60
  text "IPC-D-275 CLASS 2 LEVEL C" at 11827.23,5652 h60
  text "MIL, HOLES" at 13315.46,5539.71 h60
  text "+/-" at 12923,5539 h60
  text "+/-" at 13777,5539 h60
  text "REGISTRATION TOLERANCES:" at 11407.23,5534 h60
  text "METAL" at 12607,5534 h60
  text "5" at 13183.2,5534 h60
  text "3" at 14016.2,5534 h60
  text "MIL" at 14132.46,5534 h60
  text "MATERIAL:" at 11332.46,5324.54 h60
  text "FR-4 High Tg" at 12318.9,5184.21 h60
  text "FR-408" at 11753.46,5175.64 h60
  text "X" at 12165.46,5175.64 h60
  text "OTHER" at 13241.46,5175.64 h60
  text "62 MIL (1.6mm) +/-10%" at 12073.56,5012.92 h60
  text "THICKNESS:" at 11407.23,5008.64 h60
  text "X" at 11945.4,5008.64 h60
  text "OTHER" at 13358.46,5008.64 h60
  text "TOLERANCE:" at 11407.23,4850.64 h60
  text "X" at 12246.53,4850.64 h60
  text "ANSI IPC-6012 TYPE 3 CLASS 2" at 12433.48,4850.64 h60
  text "OTHER +/-" at 12433.46,4694.64 h60
  text "BOW & TWIST:" at 11407.23,4537.64 h60
  text "X" at 12246.53,4537.64 h60
  text "ANSI IPC-6012 TYPE 3 CLASS 2" at 12433.48,4537.64 h60
  text "OTHER +/-" at 12433.46,4379.13 h60
  text "COPPER THICKNESS (FINISHED):" at 11332.46,4243.64 h60
  text "1.4MIL (1oz)" at 12212.46,4090.92 h60
  text "2MIL (1.4oz)" at 12979.46,4090.92 h60
  text "2.8MIL (2oz)" at 13706.46,4090.92 h60
  text "OUTER:" at 11689.46,4086.64 h60
  text "X" at 12084,4086 h60
  text "1.4MIL (1oz)" at 12212.46,3933.92 h60
  text "2.8MIL (2oz)" at 12979.46,3933.92 h60
  text "N/A" at 13706,3934.29 h60
  text "INNER SIGNAL:" at 11400.38,3929.64 h60
  text "X" at 12085.42,3929.64 h60
  text "DRILLING:" at 11332.46,3790.64 h60
  text "REFERENCE:" at 11407.23,3673.64 h60
  text "X" at 12055.46,3673.64 h60
  text "AS SHOWN" at 12242.46,3673.64 h60
  text "X" at 12956.46,3673.64 h60
  text "NC_DRILL FILES" at 13093.46,3673.64 h60
  text "PTH MIN COPPER THICKNESS:" at 11407.23,3515.64 h60
  text "X" at 12757.46,3515.64 h60
  text "1MIL" at 12894.46,3515.64 h60
  text "OTHER" at 13391.46,3515.64 h60
  text "BOARD FINISH:" at 11332.46,3356.64 h60
  text "SILKSCREEN:" at 11487.68,3238.64 h60
  text "X" at 12436.46,3238.64 h60
  text "TOP" at 12562.46,3238.64 h60
  text "X" at 12946.46,3238.64 h60
  text "BOTTOM" at 13073.46,3238.64 h60
  text "SILKSCREEN COLOR:" at 11487.68,3071.64 h60
  text "X" at 12435.42,3071.64 h60
  text "WHITE" at 12562.46,3071.64 h60
  text "OTHER" at 13073.46,3071.64 h60
  text "SOLDER RESIST COLOR:" at 11487.68,2901.64 h60
  text "X" at 12055.42,2742.44 h60
  text "GREEN" at 12182.46,2742.44 h60
  text "BLUE" at 12773.46,2742.44 h60
  text "OTHER" at 13311.46,2742.44 h60
  text "IMMERSION GOLD (ENIG)" at 12393.46,2553.92 h60
  text "ENEPIG" at 13731,2550.64 h60
  text "SURFACE FINISH:" at 11332.46,2549.64 h60
  text "X" at 12206.51,2549.64 h60
  text "IMM. TIN/SILVER OR EQUIV" at 11662,2392.64 h60
  text "OTHER" at 13093.46,2392.64 h60
  text "ARRAY/PANEL:" at 11332.46,2213.64 h60
  text "CUT AND TRIM PER MECH LAYER 1" at 12393.46,2209.35 h60
  text "N.C. ROUTE" at 12393.46,2057.64 h60
  text "X" at 13072.46,2057.64 h60
  text "V. SCORE" at 13259.46,2057.64 h60
  text "CERTIFICATION:" at 11332.46,1920.64 h60
  text "MATERIALS AND WORKMANSHIP FOR ALL PCBS" at 12057.46,1920.64 h60
  text "TO MEET OR EXCEED THE REQUIREMENTS OF:" at 12057.46,1822.64 h60
  text "X" at 11683.96,1686.13 h60
  text "ANSI IPC-A-600F CLASS ->" at 11822.96,1686.13 h60
  text "X" at 13462.02,1686.13 h60
  text "2" at 13580.96,1686.14 h60
  text "1" at 13265.96,1684.64 h60
  text "3" at 13934.96,1684.64 h60
  text "X" at 11686.02,1526.64 h60
  text "UL 94V-0" at 11822.96,1526.64 h60
  text "X" at 12498.02,1526.64 h60
  text "RoHS" at 12634.96,1526.64 h60
  text "OTHER" at 13279.36,1526.64 h60
  text "PER ORDER" at 13676.42,1526.64 h60
  text "ADDITIONAL REQUIREMENTS:" at 11332.46,1385.64 h60
  text "MICROSECTION:" at 11407.23,1270.64 h60
  text "YES" at 12312.96,1270.64 h60
  text "REQUIRED" at 13174.46,1114.49 h60
  text "BARE BOARD ELEC. TEST:" at 11407.23,1111.64 h60
  text "NONE" at 12712.96,1111.64 h60
  text "X" at 13047.46,1111.64 h60
  text "PER ORDER" at 13766.46,1111.64 h60
  text "MANUFACTURER'S UL:" at 11407.23,954.64 h60
  text "RAIL" at 12572.96,950.35 h60
  text "METAL" at 13064.77,950.35 h60
  text "X" at 13440,950 h60
  text "SILK" at 13576.46,950.35 h60
  text ".Layer_Name" at 577,-858.49 h60
M11 Gerber Information:
  lines w10: -292,-930.17 6308,-930.17 ; -292,-726.83 6310,-726.83 ; -292,-523.5 -292,-1133.5 3713,-1133.5 6310,-1133.5 6310,-523.5 -291.5,-523.5 -291.5,-1133.5 1284,-1133.5 ; 2173,-1133.5 2173,-523.5 ; 3440,-726.83 3440,-523.5 ; 4280,-726.83 4280,-523.5 ; 4902,-1140 4902,-937.17
  text "ALL ARTWORK VIEWED FROM TOP SIDE" at -228.5,-655.67 h60
  text "BOARD #:" at 2248,-655.67 h60
  text ".PRJ_Number" at 2793.5,-655.67 h60
  text "REV:" at 3638,-655.67 h60
  text ".PCB_Rev" at 3929.5,-655.67 h60
  text "SVN REV:" at 4476,-655.67 h60
  text ".VersionControl_RevNumber" at 4982,-655.67 h60
  text "LAYER NAME =" at -228.5,-858.49 h60
  text "PLOT NAME =" at -228.5,-1064.34 h60
  text ".plot_File_Name" at 577,-1064.34 h60
  text "GENERATED    :" at 2250,-1064.34 h60
  text ".Print_Date" at 3119.5,-1064.34 h60
  text ".Print_Time" at 3848.5,-1064.34 h60
  text "TEXAS INSTRUMENTS" at 5113,-1064.34 h60
M12 Stackup:
  lines w6: 11360,7460 13910,7460 ; 11360,7564.4 13910,7564.4 ; 11300,6975 ccw(c11334,6975) 11334,6941 13936,6941 ccw(c13936,6975) 13970,6975 13970,7681 ccw(c13936,7681) 13936,7715 11334,7715 ccw(c11334,7681) 11300,7681 11300,6975
  text "The Stackup Legend below this is static." at 11605.5,7874.5 h60
  text "If you change the stackup, update the Legend." at 11615.5,7784.5 h60
  text "Layer Stack Up Detail for: Ref_Design.PcbDoc" at 11360,7597.1 h57
  text "Layer" at 11360,7525.4 h24
  text "Gerber" at 12255.81,7525.4 h24
  text "Copper" at 12819.33,7525.4 h24
  text "Dielectric" at 13422.04,7525.4 h24
  text "Name" at 11360,7477.4 h24
  text "Document" at 12255.81,7477.4 h24
  text "Thickness" at 12819.33,7477.4 h24
  text "Material" at 13422.04,7477.4 h24
  text "Top Solder Mask" at 11360,7384.44 h34
  text "(.GTS)" at 12255.81,7384.44 h34
  text "Solder Resist" at 13422.04,7384.44 h34
  text "Top Layer" at 11360,7287.69 h34
  text "(.GTL)" at 12255.81,7287.69 h34
  text "1.4mil" at 12819.33,7287.69 h34
  text "FR-4" at 13422.04,7239.31 h34
  text "Bottom Layer" at 11360,7190.94 h34
  text "(.GBL)" at 12255.81,7190.94 h34
  text "1.4mil" at 12819.33,7190.94 h34
  text "Bottom Solder Mask" at 11360,7094.19 h34
  text "(.GBS)" at 12255.81,7094.19 h34
  text "Solder Resist" at 13422.04,7094.19 h34
  text ".Layer_Name" at 577,-858.49 h60
M13 Component Bodies Top:
  text ".Layer_Name" at 577,-858.49 h60
M14 Component Bodies Bottom:
  text ".Layer_Name" at 577,-858.49 h60
M15 Courtyards Top:
  text ".Layer_Name" at 577,-858.49 h60
M16 Courtyards Bottom:
  text ".Layer_Name" at 577,-858.49 h60
Drill Drawing:
  text ".Layer_Name" at 577,-858.49 h60

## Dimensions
-10.83,-31.5 to 1538.39,-28.54 on M2 Board Dimensions
-47.24,-11.81 to -150.59,1144.68 on M2 Board Dimensions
